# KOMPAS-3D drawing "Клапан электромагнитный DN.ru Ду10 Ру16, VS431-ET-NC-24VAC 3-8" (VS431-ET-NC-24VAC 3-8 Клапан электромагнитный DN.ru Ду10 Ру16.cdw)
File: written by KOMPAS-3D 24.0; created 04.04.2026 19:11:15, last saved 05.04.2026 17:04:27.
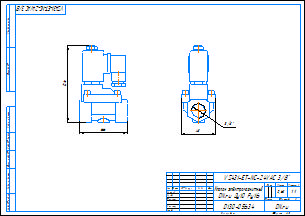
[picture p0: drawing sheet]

Document properties: c3d_UniqueCompID: ef56311e-7521-43dc-8291-0e6108b3d81d; Обозначение: VS400-ET-NC-220VAC 3-8; Наименование: Клапан электромагнитный DN.ru Ду10 Ру16; Автор: artio; Класс точности: c; Знак неуказанной шероховатости: Шероховатость не задана; Рассекать на разрезах: Да; Автор: artio; Форматы листов документа: A3; Полное имя файла: VS431-ET-NC-24VAC 3-8 Клапан электромагнитный DN.ru Ду10 Ру16.m3d; Масса: 0.62; Наименование: Клапан электромагнитный DN.ru Ду10 Ру16; Количество листов документа: 1; Примечание: D130-05634

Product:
- Body: Тело 1  | qty 1
    Масса: 1.030062
- Part/product: Клапан электромагнитный DN.ru Ду10 Ру16  | designation VS431-ET-NC-24VAC 3-8
    Масса: 0.62
    Раздел спецификации: Прочие изделия
    Примечание: D130-05634
    additional columns: ef56311e-7521-43dc-8291-0e6108b3d81d; VS400-ET-NC-220VAC 3-8; artio; c; Шероховатость не задана; Да

Views: Вид 1, Спереди, Проекционный вид 2
Referenced files in C:\Users\artio\OneDrive\Рабочий стол\Клапан электромагнитный DN.ru\VS400-ET-NC\VS400-ET-NC-24VDC\: VS400-ET-NC-24VDC 3-8 Клапан электромагнитный DN.ru Ду10 Ру16.m3d
Referenced files in C:\Users\artio\OneDrive\Рабочий стол\Клапан электромагнитный DN.ru\VS431\VS431-ET-NC\VS431-ET-NC-24VAC\Ду10\: VS431-ET-NC-24VAC 3-8 Клапан электромагнитный DN.ru Ду10 Ру16.m3d
Referenced files in C:\Users\artio\OneDrive\Рабочий стол\Клапан электромагнитный DN.ru\VS400-ET-NC\: VS400-ET-NC-24VDC 3-8 Клапан электромагнитный DN.ru Ду10 Ру16.cdw
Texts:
  VS431-ET-NC-24VAC 3-8
  Клапан электромагнитный
  DN.ru Ду10 Ру16
  VS431-ET-NC-24VAC 3/8"
  VS431-ET-NC-24VAC 3/8"-
  Клапан электромагнитный DN.ru Ду10 Ру16
  VS431-ET-NC-24VAC 3-8 Клапан электромагнитный DN.ru Ду10 Ру16
Dimensions and other numbers on the sheet: 0; 3; 2; 4; 48; 3/8"; 66; 106; 1:1; 1; 0,62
